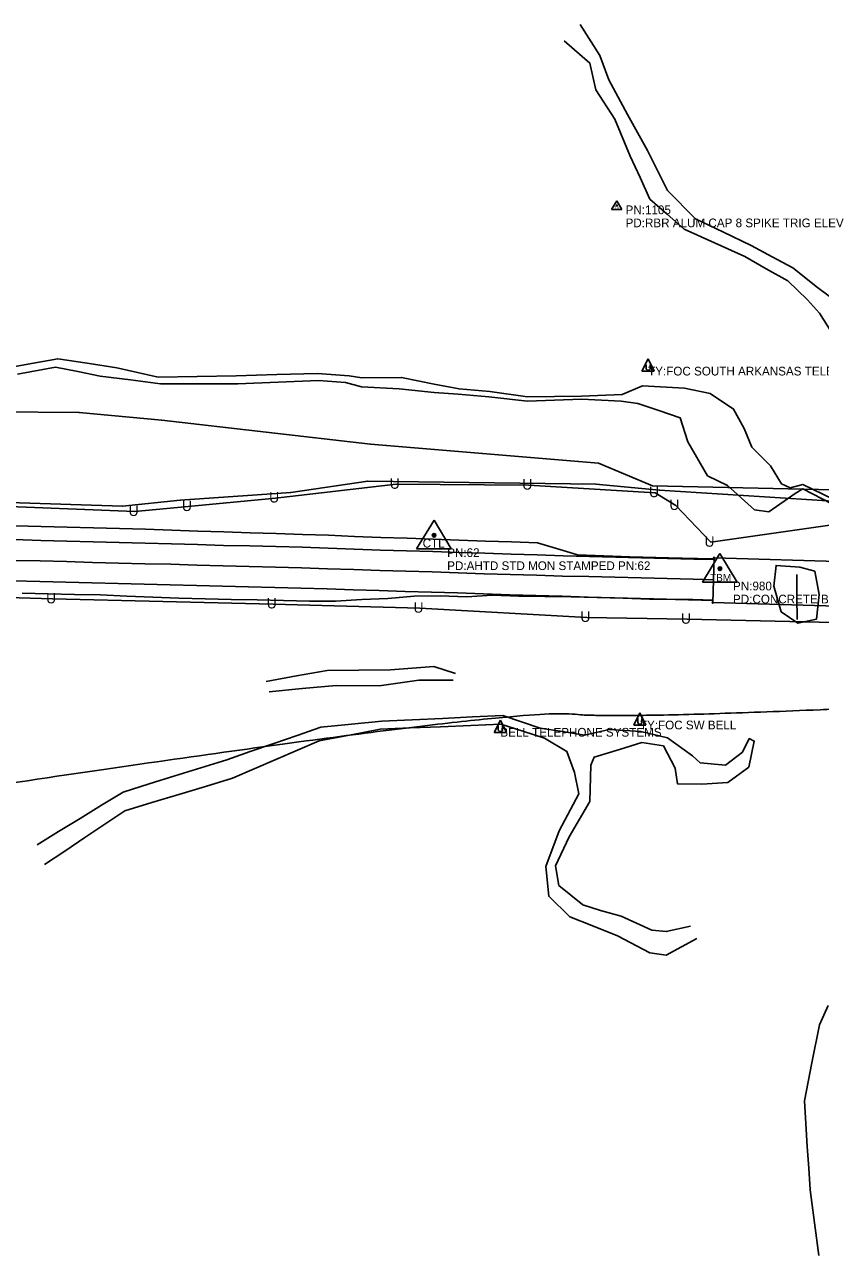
# Model space of a CAD drawing. Extents: x 976456 to 985170, y 1525951 to 1527080.
# Drawn here: x 982425 to 982881, y 1525951 to 1526657 of the extents above; entities that cross this region are included whole.
import ezdxf

# ---------------------------------------------------------------- set-up
doc = ezdxf.new("R2010")
doc.units = 0
for name, color, linetype in [('Default', 7, 'Continuous'), ('S_BRIDGE', 7, 'Continuous'), ('S_DITCHLINE', 7, 'Continuous'), ('S_EDGE_PAVEMENT', 7, 'Continuous'), ('S_FIBER_OPTIC_CABLE', 7, 'Continuous'), ('S_PAVEMENT_CROWN', 7, 'Continuous'), ('S_PRIMARY_CTL', 7, 'Continuous'), ('S_PRIMARY_CTL_ANNOT', 7, 'Continuous'), ('S_SECONDARY_CTL', 7, 'Continuous'), ('S_SECONDARY_CTL_ANNOT', 7, 'Continuous'), ('S_SHOULDER', 7, 'Continuous'), ('S_STR_PT_SYM', 7, 'Continuous'), ('S_STREAM', 7, 'Continuous'), ('S_UNDERGROUND_CABLE', 7, 'Continuous'), ('S_UTILITY_POLE_ANNOT', 7, 'Continuous'), ('S_UTL_PT_SYM', 7, 'Continuous')]:
    doc.layers.add(name, color=color, linetype=linetype)

msp = doc.modelspace()

# ---------------------------------------------------------------- linework, layer by layer
at = {"layer": 'S_BRIDGE'}
for p, q in [((982820.35, 1526351.36), (982819.62, 1526325.75)), ((982981.23, 1526346.76), (982820.35, 1526351.36)), ((982819.62, 1526325.75), (982980.5, 1526321.2))]:
    msp.add_line(p, q, dxfattribs=at)
at = {"layer": 'S_DITCHLINE'}
for points in [[(982888.65, 1526385.06), (982871.35, 1526393.51), (982863.99, 1526391.57), (982859.15, 1526393.88), (982852.79, 1526404.14), (982842.06, 1526414.93), (982837.67, 1526425.55), (982831.58, 1526436.71), (982818.1, 1526445.59), (982803.39, 1526448.64), (982779.21, 1526449.97), (982767.64, 1526445.04), (982744.22, 1526444.16), (982728.78, 1526443.97), (982713.34, 1526443.78), (982691.6, 1526446.73), (982674.02, 1526448.29), (982659.61, 1526451.04), (982641, 1526454.86), (982618.12, 1526454.66), (982610.97, 1526455.75), (982592.71, 1526457.06), (982569.34, 1526456.46), (982545.96, 1526455.85), (982523.57, 1526455.45), (982501.17, 1526455.04), (982477.51, 1526460.44), (982460.56, 1526463.01), (982443.61, 1526465.58), (982429.78, 1526463.11), (982415.96, 1526460.65)], [(982887.9, 1526382.42), (982871.26, 1526391.03), (982866.87, 1526388.25), (982851.77, 1526377.69), (982843.62, 1526378.99), (982828.12, 1526392.88), (982816.67, 1526398.43), (982805.21, 1526417.93), (982800.96, 1526431.72), (982788.73, 1526435.83), (982776.51, 1526439.95), (982767.08, 1526441.16), (982744.38, 1526442.39), (982728.8, 1526441.82), (982713.21, 1526441.25), (982691.06, 1526443.71), (982673.41, 1526445.29), (982659.61, 1526446.31), (982639.68, 1526448.38), (982618.02, 1526449.5), (982608.8, 1526451.88), (982593.23, 1526453.11), (982570.11, 1526452.11), (982547, 1526451.12), (982524.82, 1526451.15), (982502.65, 1526451.17), (982485.34, 1526453.43), (982468.03, 1526455.68), (982455.22, 1526458.21), (982442.41, 1526460.73), (982420.45, 1526456.65)], [(982868.09, 1526315.99), (982867.95, 1526328.88), (982867.8, 1526341.8)], [(982671.86, 1526285.03), (982659.49, 1526289.06), (982647.02, 1526288.14), (982634.55, 1526287.23), (982616.41, 1526286.97), (982598.26, 1526286.71), (982580.73, 1526283.61), (982563.2, 1526280.51)], [(982670.58, 1526281.18), (982650.88, 1526281.25), (982628.14, 1526277.88), (982603.43, 1526278.19), (982583.94, 1526276.51), (982565.05, 1526274.5)], [(982806.84, 1526140.14), (982792.88, 1526136.97), (982784.65, 1526137.83), (982767.06, 1526145.78), (982755.08, 1526149.03), (982745.09, 1526152.35), (982731.19, 1526163.52), (982729.42, 1526174.76), (982737.19, 1526191.43), (982749.08, 1526211.61), (982749.62, 1526232.48), (982751.54, 1526237.14), (982766.17, 1526241.53), (982778.81, 1526245.51), (982791.3, 1526243.51), (982797.99, 1526230.64), (982799.41, 1526221.71), (982813.27, 1526221.57), (982828.35, 1526222.49), (982840.3, 1526231.33), (982843.47, 1526246.29), (982840.56, 1526247.74), (982836.73, 1526239.95), (982826.92, 1526232.45), (982812.41, 1526233.85), (982808.06, 1526237.79), (982793.62, 1526248.23), (982778.39, 1526251.8), (982760.12, 1526252.98), (982746.02, 1526249.73), (982733.28, 1526251.74), (982720.54, 1526253.75), (982699.04, 1526260.98), (982681.71, 1526260.14), (982664.38, 1526259.3), (982647.05, 1526258.46), (982629.72, 1526257.62), (982612.16, 1526255.89), (982594.6, 1526254.17), (982581.12, 1526249.52), (982567.64, 1526244.87), (982554.16, 1526240.22), (982540.69, 1526235.57), (982525.8, 1526230.94), (982510.92, 1526226.3), (982496.04, 1526221.66), (982481.16, 1526217.02), (982468.82, 1526209.46), (982456.48, 1526201.9), (982444.14, 1526194.34), (982431.8, 1526186.78)], [(982810.54, 1526133.04), (982792.83, 1526123.54), (982783.55, 1526124.89), (982764.88, 1526134.55), (982751.19, 1526140.04), (982737.49, 1526145.53), (982725.42, 1526157.24), (982723.82, 1526174.25), (982731.39, 1526194.71), (982742.76, 1526216.04), (982740.15, 1526228.29), (982735.92, 1526240.38), (982723.04, 1526247.9), (982710.5, 1526251.91), (982697.97, 1526255.92), (982680.65, 1526255.21), (982663.33, 1526254.5), (982646.01, 1526253.78), (982628.69, 1526253.07), (982611.15, 1526249.71), (982593.62, 1526246.36), (982581.19, 1526241.01), (982568.77, 1526235.65), (982556.35, 1526230.3), (982543.92, 1526224.95), (982528.49, 1526220.29), (982513.06, 1526215.64), (982497.62, 1526210.98), (982482.19, 1526206.32), (982470.67, 1526198.59), (982459.15, 1526190.87), (982447.63, 1526183.15), (982436.11, 1526175.42)]]:
    msp.add_lwpolyline(points, dxfattribs=at)
msp.add_lwpolyline([(982880.78, 1526330.43), (982878.2, 1526343.71), (982869.55, 1526346.06), (982855.98, 1526347.01), (982854.59, 1526335.11), (982858.79, 1526320.49), (982868.41, 1526313.9), (982879.18, 1526316.22)], close=True, dxfattribs=at)
at = {"layer": 'S_EDGE_PAVEMENT'}
for points in [[(982418.88, 1526361.81), (982433.88, 1526361.38), (982448.87, 1526361), (982463.86, 1526360.61), (982478.86, 1526360.18), (982493.85, 1526359.83), (982508.85, 1526359.36), (982523.85, 1526358.95), (982538.84, 1526358.5), (982553.84, 1526358.22), (982568.84, 1526357.81), (982583.83, 1526357.41), (982598.83, 1526357.01), (982613.81, 1526356.44), (982628.87, 1526355.85), (982643.87, 1526355.44), (982658.86, 1526354.96), (982673.85, 1526354.48), (982688.84, 1526353.99), (982703.83, 1526353.52), (982718.75, 1526353.05), (982733.74, 1526352.52), (982748.73, 1526352.19), (982763.73, 1526351.81), (982778.73, 1526351.47), (982793.72, 1526351.06), (982808.72, 1526350.68), (982819.9, 1526350.42)], [(982418.27, 1526338.21), (982433.26, 1526337.82), (982433.26, 1526337.82), (982448.26, 1526337.42), (982463.25, 1526337.05), (982478.25, 1526336.74), (982493.24, 1526336.3), (982493.24, 1526336.3), (982508.23, 1526335.86), (982523.22, 1526335.51), (982538.22, 1526335.12), (982553.21, 1526334.73), (982568.21, 1526334.34), (982583.2, 1526333.92), (982598.2, 1526333.51), (982613.19, 1526333.07), (982628.12, 1526332.6), (982643.12, 1526332.14), (982658.11, 1526331.67), (982673.1, 1526331.22), (982688.09, 1526330.7), (982703.09, 1526330.19), (982718.14, 1526329.73), (982733.14, 1526329.31), (982748.13, 1526328.9), (982763.13, 1526328.5), (982778.12, 1526328.09), (982778.12, 1526328.09), (982793.12, 1526327.72), (982793.12, 1526327.72), (982808.11, 1526327.39), (982819.58, 1526327.12)]]:
    msp.add_lwpolyline(points, dxfattribs=at)
at = {"layer": 'S_FIBER_OPTIC_CABLE'}
for p, q in [((982455.93, 1526434.73), (982354.59, 1526435.59)), ((982503.29, 1526430.31), (982455.93, 1526434.73)), ((982623.16, 1526416.65), (982503.29, 1526430.31)), ((982754.01, 1526405.74), (982623.16, 1526416.65)), ((982785, 1526392.62), (982754.01, 1526405.74)), ((982621.59, 1526395.37), (982577.33, 1526388.86)), ((982752.57, 1526393.67), (982621.59, 1526395.37)), ((982789.05, 1526390.17), (982752.57, 1526393.67)), ((982925.97, 1526389.54), (982785, 1526392.62)), ((982577.33, 1526388.86), (982513.95, 1526384.55)), ((982928.07, 1526381.47), (982789.05, 1526390.17)), ((982480.84, 1526381.04), (982415.76, 1526383.16)), ((982513.95, 1526384.55), (982480.84, 1526381.04))]:
    msp.add_line(p, q, dxfattribs=at)
msp.add_open_spline([(983038.02, 1526271.95), (982776.59, 1526257.91), (982699.02, 1526265.54), (982301.76, 1526204.82)], degree=2, dxfattribs=at)
at = {"layer": 'S_PAVEMENT_CROWN'}
msp.add_lwpolyline([(982418.57, 1526349.94), (982433.57, 1526349.58), (982433.57, 1526349.58), (982448.56, 1526349.19), (982463.56, 1526348.8), (982463.56, 1526348.8), (982478.55, 1526348.41), (982493.55, 1526348.02), (982493.55, 1526348.02), (982508.54, 1526347.67), (982523.54, 1526347.27), (982538.53, 1526346.88), (982538.53, 1526346.88), (982553.52, 1526346.42), (982553.52, 1526346.42), (982568.52, 1526346.02), (982583.51, 1526345.62), (982583.51, 1526345.62), (982598.51, 1526345.15), (982598.51, 1526345.15), (982613.5, 1526344.71), (982613.5, 1526344.71), (982628.5, 1526344.21), (982643.49, 1526343.71), (982658.48, 1526343.29), (982673.47, 1526342.71), (982673.47, 1526342.71), (982688.46, 1526342.22), (982703.46, 1526341.74), (982703.46, 1526341.74), (982718.45, 1526341.4), (982733.44, 1526340.94), (982748.43, 1526340.6), (982748.43, 1526340.6), (982763.43, 1526340.21), (982763.43, 1526340.21), (982778.42, 1526339.82), (982793.42, 1526339.48), (982793.42, 1526339.48), (982808.42, 1526339.09), (982819.62, 1526338.8)], dxfattribs=at)
at = {"layer": 'S_PRIMARY_CTL'}
for p, q in [((982659.67, 1526373.07), (982649.63, 1526356.55)), ((982659.67, 1526373.07), (982669.49, 1526356.55)), ((982649.63, 1526356.55), (982669.49, 1526356.55)), ((982823.73, 1526353.92), (982813.69, 1526337.4)), ((982823.73, 1526353.92), (982833.55, 1526337.4)), ((982813.69, 1526337.4), (982833.55, 1526337.4))]:
    msp.add_line(p, q, dxfattribs=at)
for centre, radius in [((982659.67, 1526364.37), 1.04), ((982659.67, 1526364.37), 0.609), ((982659.67, 1526364.37), 0.344), ((982823.73, 1526345.22), 1.04), ((982823.73, 1526345.22), 0.609), ((982823.73, 1526345.22), 0.344)]:
    msp.add_circle(centre, radius, dxfattribs=at)
at = {"layer": 'S_SECONDARY_CTL'}
for p, q in [((982764.56, 1526556.12), (982761.55, 1526551.16)), ((982764.56, 1526556.12), (982767.51, 1526551.16)), ((982761.55, 1526551.16), (982767.51, 1526551.16))]:
    msp.add_line(p, q, dxfattribs=at)
for radius in [0.311, 0.183, 0.103]:
    msp.add_circle((982764.56, 1526553.51), radius, dxfattribs=at)
at = {"layer": 'S_SHOULDER'}
for points in [[(982419.09, 1526369.66), (982434.09, 1526369.34), (982449.08, 1526368.96), (982464.08, 1526368.57), (982479.07, 1526368.22), (982494.07, 1526367.87), (982509.06, 1526367.34), (982524.06, 1526366.75), (982539.05, 1526366.21), (982554.05, 1526365.77), (982569.04, 1526365.26), (982584.03, 1526364.84), (982599.03, 1526364.44), (982614.01, 1526363.67), (982629.11, 1526363.08), (982644.1, 1526362.67), (982659.09, 1526362.07), (982674.08, 1526361.48), (982689.07, 1526360.91), (982704.06, 1526360.53), (982718.93, 1526360.06), (982733.82, 1526355.66), (982742.03, 1526353.08), (982757.02, 1526352.47), (982772.02, 1526352.05), (982787.01, 1526351.63), (982802, 1526351.17), (982819.91, 1526350.73)], [(982423.22, 1526331.21), (982438.21, 1526330.64), (982453.21, 1526330.39), (982468.2, 1526330.15), (982483.19, 1526329.49), (982498.18, 1526328.83), (982513.16, 1526328.26), (982528.15, 1526327.89), (982543.15, 1526327.57), (982558.15, 1526327.33), (982573.14, 1526326.98), (982588.14, 1526326.53), (982603.14, 1526326.46), (982618.09, 1526327.49), (982633.11, 1526328.12), (982648.16, 1526329.31), (982663.18, 1526329.64), (982678.17, 1526329.08), (982693.2, 1526329.94), (982708.2, 1526329.48), (982723.27, 1526329.24), (982738.26, 1526328.94), (982753.26, 1526328.58), (982768.25, 1526328.17), (982783.25, 1526327.74), (982798.24, 1526327.39), (982813.24, 1526327.07), (982819.62, 1526326.9)]]:
    msp.add_lwpolyline(points, dxfattribs=at)
at = {"layer": 'S_STR_PT_SYM'}
for points in [[(982820.35, 1526351.36), (982820.35, 1526351.86), (982820.35, 1526351.36), (982819.85, 1526351.36), (982820.35, 1526351.36), (982820.35, 1526350.86), (982820.35, 1526351.36), (982820.85, 1526351.36)], [(982819.62, 1526325.75), (982819.62, 1526326.25), (982819.62, 1526325.75), (982819.12, 1526325.75), (982819.62, 1526325.75), (982819.62, 1526325.25), (982819.62, 1526325.75), (982820.12, 1526325.75)]]:
    msp.add_lwpolyline(points, dxfattribs=at)
at = {"layer": 'S_STREAM'}
for points in [[(982895.93, 1526493.93), (982890.81, 1526498.19), (982879.82, 1526506.47), (982865.52, 1526517.79), (982853.63, 1526524.12), (982841.74, 1526530.45), (982825.71, 1526538.15), (982809.69, 1526545.84), (982793.64, 1526562.16), (982787.89, 1526573.62), (982782.15, 1526585.07), (982770.67, 1526605.65), (982759.87, 1526625.52), (982754.88, 1526639.53), (982743.5, 1526657.24)], [(982891.35, 1526475.16), (982880.94, 1526491.73), (982874.03, 1526499.44), (982862.71, 1526510.26), (982850.35, 1526517.25), (982837.99, 1526524.24), (982820.56, 1526532.09), (982803.12, 1526539.94), (982793.35, 1526548.54), (982783.58, 1526557.14), (982777.88, 1526569.48), (982772.19, 1526581.81), (982763.31, 1526603.03), (982752.41, 1526619.92), (982749.05, 1526635.2), (982734.39, 1526647.94)], [(982880.45, 1525951.26), (982878, 1525970.02), (982875.54, 1525988.77), (982874.67, 1526001.26), (982873.79, 1526013.75), (982873.02, 1526026.87), (982872.26, 1526039.98), (982876.56, 1526061.77), (982880.87, 1526083.56), (982885.84, 1526094.66)]]:
    msp.add_lwpolyline(points, dxfattribs=at)
at = {"layer": 'S_UNDERGROUND_CABLE'}
for p, q in [((982782.49, 1526465.52), (982778.97, 1526458.43)), ((982782.49, 1526465.52), (982785.98, 1526458.43)), ((982778.97, 1526458.43), (982785.98, 1526458.43)), ((982781.29, 1526459.67), (982781.29, 1526462.11)), ((982781.91, 1526459.01), (982781.29, 1526459.67)), ((982783.11, 1526459.01), (982781.91, 1526459.01)), ((982783.65, 1526459.67), (982783.11, 1526459.01)), ((982783.65, 1526462.11), (982783.65, 1526459.67)), ((982637.81, 1526393.55), (982568.58, 1526385.64)), ((982713.91, 1526393.06), (982637.81, 1526393.55)), ((982786.64, 1526388.71), (982713.91, 1526393.06)), ((982568.58, 1526385.64), (982518.49, 1526380.77)), ((982798.33, 1526381.39), (982786.64, 1526388.71)), ((982487.89, 1526377.93), (982415.84, 1526380.92)), ((982518.49, 1526380.77), (982487.89, 1526377.93)), ((982818.47, 1526360.31), (982798.33, 1526381.39)), ((982950.31, 1526379.17), (982818.47, 1526360.31)), ((982440.57, 1526327.81), (982218.12, 1526334.59)), ((982567.2, 1526324.9), (982440.57, 1526327.81)), ((982651.43, 1526322.47), (982567.2, 1526324.9)), ((982747.23, 1526317.16), (982651.43, 1526322.47)), ((982804.96, 1526316.13), (982747.23, 1526317.16)), ((983029.83, 1526311.42), (982804.96, 1526316.13)), ((982697.7, 1526258.36), (982694.17, 1526251.26)), ((982697.7, 1526258.36), (982701.19, 1526251.26)), ((982777.79, 1526262.54), (982774.26, 1526255.45)), ((982776.59, 1526256.69), (982776.59, 1526259.13)), ((982777.79, 1526262.54), (982781.28, 1526255.45)), ((982778.95, 1526259.13), (982778.95, 1526256.69)), ((982694.17, 1526251.26), (982701.19, 1526251.26)), ((982696.5, 1526252.5), (982696.5, 1526254.95)), ((982697.12, 1526251.85), (982696.5, 1526252.5)), ((982698.32, 1526251.85), (982697.12, 1526251.85)), ((982698.86, 1526252.5), (982698.32, 1526251.85)), ((982698.86, 1526254.95), (982698.86, 1526252.5)), ((982774.26, 1526255.45), (982781.28, 1526255.45)), ((982777.21, 1526256.03), (982776.59, 1526256.69)), ((982778.41, 1526256.03), (982777.21, 1526256.03)), ((982778.95, 1526256.69), (982778.41, 1526256.03))]:
    msp.add_line(p, q, dxfattribs=at)
at = {"layer": 'S_UTL_PT_SYM'}
for points in [[(982455.93, 1526434.73), (982455.93, 1526434.78), (982455.93, 1526434.73), (982455.88, 1526434.73), (982455.93, 1526434.73), (982455.93, 1526434.68), (982455.93, 1526434.73), (982455.98, 1526434.73)], [(982503.29, 1526430.31), (982503.29, 1526430.36), (982503.29, 1526430.31), (982503.24, 1526430.31), (982503.29, 1526430.31), (982503.29, 1526430.26), (982503.29, 1526430.31), (982503.34, 1526430.31)], [(982623.16, 1526416.65), (982623.16, 1526416.7), (982623.16, 1526416.65), (982623.11, 1526416.65), (982623.16, 1526416.65), (982623.16, 1526416.6), (982623.16, 1526416.65), (982623.21, 1526416.65)], [(982754.01, 1526405.74), (982754.01, 1526405.79), (982754.01, 1526405.74), (982753.96, 1526405.74), (982754.01, 1526405.74), (982754.01, 1526405.69), (982754.01, 1526405.74), (982754.06, 1526405.74)], [(982621.59, 1526395.37), (982621.59, 1526395.42), (982621.59, 1526395.37), (982621.54, 1526395.37), (982621.59, 1526395.37), (982621.59, 1526395.32), (982621.59, 1526395.37), (982621.64, 1526395.37)], [(982752.57, 1526393.67), (982752.57, 1526393.72), (982752.57, 1526393.67), (982752.52, 1526393.67), (982752.57, 1526393.67), (982752.57, 1526393.62), (982752.57, 1526393.67), (982752.62, 1526393.67)], [(982785, 1526392.62), (982785, 1526392.67), (982785, 1526392.62), (982784.95, 1526392.62), (982785, 1526392.62), (982785, 1526392.57), (982785, 1526392.62), (982785.05, 1526392.62)], [(982577.33, 1526388.86), (982577.33, 1526388.91), (982577.33, 1526388.86), (982577.28, 1526388.86), (982577.33, 1526388.86), (982577.33, 1526388.81), (982577.33, 1526388.86), (982577.38, 1526388.86)], [(982789.05, 1526390.17), (982789.05, 1526390.22), (982789.05, 1526390.17), (982789, 1526390.17), (982789.05, 1526390.17), (982789.05, 1526390.12), (982789.05, 1526390.17), (982789.1, 1526390.17)], [(982480.84, 1526381.04), (982480.84, 1526381.09), (982480.84, 1526381.04), (982480.79, 1526381.04), (982480.84, 1526381.04), (982480.84, 1526380.99), (982480.84, 1526381.04), (982480.89, 1526381.04)], [(982513.95, 1526384.55), (982513.95, 1526384.6), (982513.95, 1526384.55), (982513.9, 1526384.55), (982513.95, 1526384.55), (982513.95, 1526384.5), (982513.95, 1526384.55), (982514, 1526384.55)]]:
    msp.add_lwpolyline(points, dxfattribs=at)

# ---------------------------------------------------------------- texts
at = {"layer": 'Default'}
for p in [(982634.18, 1526391.01), (982710.28, 1526390.51), (982564.95, 1526383.1), (982783.01, 1526386.16), (982484.27, 1526375.38), (982514.86, 1526378.23), (982794.7, 1526378.84), (982814.84, 1526357.76), (982436.94, 1526325.26), (982563.57, 1526322.36), (982647.8, 1526319.92), (982743.6, 1526314.62), (982801.33, 1526313.59)]:
    msp.add_text('U', height=6, rotation=360, dxfattribs=at).set_placement(p)
at = {"layer": 'S_PRIMARY_CTL'}
for s, height, p in [('CTL', 5, (982653.08, 1526357.29)), ('TBM', 4.287, (982818.07, 1526337.83))]:
    msp.add_text(s, height=height, rotation=360, dxfattribs=at).set_placement(p)
at = {"layer": 'S_PRIMARY_CTL_ANNOT'}
for s, p in [('PN:62', (982667.17, 1526351.87)), ('PD:AHTD STD MON STAMPED PN:62', (982667.17, 1526344.37)), ('PN:980', (982831.23, 1526332.72)), ('PD:CONCRETE BRIDGE END', (982831.23, 1526325.22))]:
    msp.add_text(s, height=5, dxfattribs=at).set_placement(p)
at = {"layer": 'S_SECONDARY_CTL'}
msp.add_text('TV', height=1.5, rotation=360, dxfattribs=at).set_placement((982763.35, 1526551.5))
at = {"layer": 'S_SECONDARY_CTL_ANNOT'}
for s, p in [('PN:1105', (982769.56, 1526548.51)), ('PD:RBR ALUM CAP 8 SPIKE TRIG ELEV', (982769.56, 1526541.01))]:
    msp.add_text(s, height=5, dxfattribs=at).set_placement(p)
at = {"layer": 'S_UTILITY_POLE_ANNOT'}
for s, p in [('TY:FOC SOUTH ARKANSAS TELEPHONE', (982782.49, 1526455.99)), ('BELL TELEPHONE SYSTEMS', (982697.7, 1526248.82)), ('TY:FOC SW BELL', (982777.79, 1526253))]:
    msp.add_text(s, height=5, dxfattribs=at).set_placement(p)

doc.saveas('drawing.dxf')
